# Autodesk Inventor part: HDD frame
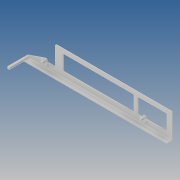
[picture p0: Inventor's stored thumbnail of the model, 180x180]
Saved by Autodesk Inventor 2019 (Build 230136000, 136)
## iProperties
Created: 2021-02
Part Number: HDD frame
Material: Všeobecné
Document SubType Name: Modeling
Designer: Martin Kočka
Density: 1 g/cm^3
Appearance: Výchozí
Author: Martin Kočka
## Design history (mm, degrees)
sketch "Náčrt1"
  geometry: L1 (-44.5, 13)-(75.5, 13); L2 (75.5, 13)-(75.5, -13); L3 (75.5, -13)-(-73.5, -13); L4 (-136.949, 0)-(119.471, 0) reference; L5 (0, -18.2)-(0, 18.2) reference; L6 (-36.5, 9)-(36.5, 9); L7 (36.5, 9)-(36.5, -7); L8 (36.5, -7)-(-36.5, -7); L9 (-36.5, -7)-(-36.5, 9); L10 (-44.5, -7)-(-44.5, 13); L11 (40.5, 9)-(70.5, 9); L12 (70.5, 9)-(70.5, -7); L13 (40.5, -7)-(40.5, 9); L14 (-100.317, -6.15)-(82.839, -6.15); L15 (-73.5, -13)-(-73.5, -11); L16 (-52.95, -6.15)-(-52.95, -7); L17 (-52.95, -7)-(-44.5, -7); L18 (45.35, -7)-(45.35, -6.15); L19 (48.65, -6.15)-(48.65, -7); L20 (-73.5, -11)-(-55.144, -4.592); L21 (45.35, -7)-(40.5, -7); L22 (70.5, -7)-(48.65, -7); C1 r 1.25 at (47, -6.15); A1 r 1.65 centre (47, -6.15) between (45.586, -7) and (45.35, -6.15); A2 r 1.65 centre (-54.6, -6.15) between (-52.95, -6.15) and (-55.144, -4.592); A3 r 1.65 centre (-54.6, -6.15) between (-52.95, -6.15) and (-55.144, -4.592); A4 r 1.65 centre (47, -6.15) between (48.65, -6.15) and (45.35, -6.15); 3 further points
  constraints: 40 end point, 8 parallel, 8 point on circle, 6 perpendicular, 5 centre point, 5 coincident, 5 point on line, 4 collinear, 4 tangent, 3 horizontal, 1 concentric, 1 vertical, 2 other
  dimensions: "d1" = 26 distance of L1.end L2.end; "d3" = 39 distance between parallel lines of L7 L2; "d4" = 6 distance between parallel lines of L3 L8; "d5" = 4 distance between parallel lines of L1 L6; "d6" = 28.5 distance from line of L2 point (47, -6.15); "d7" = 101.6 distance of point (47, -6.15) point (-54.6, -6.15); "d8" = 2.5 diameter of C1; "d10" = 6.85 distance between parallel lines of L3 L14; "d11" = 5 distance between parallel lines of L12 L2; "d12" = 4 distance between parallel lines of L7 L13; "d13" = 8 distance between parallel lines of L9 L10; "d14" = 112 distance between parallel lines of L2 L9; "d15" = 3.3 diameter of A1; "d17" = 149 distance of L2.end L3.end; "d18" = 3.3 diameter of A2; "d19" = 2 distance from line of L15.end L3
extrude "Vysunutí1" new body sketch "Náčrt1" distance "d20" = 0.9; taper "d21" = 0 deg
fillet "Zaoblení1" dims "d22" = 1
sketch "Náčrt2"
  geometry: L1 (74.5, 13)-(-43.5, 13) reference; L2 (-44.5, 12)-(-44.5, -6) reference; L3 (-45.5, -7)-(-51.954, -7) reference; L4 (-55.144, -4.592)-(-73.5, -11) reference; L5 (-73.5, -11)-(-73.5, -13) reference; L6 (-73.5, -13)-(75.5, -13) reference; L7 (75.5, -13)-(75.5, 12) reference; L8 (35.5, -7)-(-35.5, -7) reference; L9 (-36.5, -6)-(-36.5, 8) reference; L10 (-35.5, 9)-(35.5, 9) reference; L11 (36.5, 8)-(36.5, -6) reference; L12 (70.5, 8)-(70.5, -6) reference; L13 (69.5, -7)-(49.646, -7) reference; L14 (44.354, -7)-(41.5, -7) reference; L15 (40.5, -6)-(40.5, 8) reference; L16 (41.5, 9)-(69.5, 9) reference; L17 (-58.584, -5.793)-(-55.144, -4.592); L18 (-45.5, -7)-(-51.954, -7) reference; L19 (-50.691, -7)-(-51.954, -7); L20 (44.354, -7)-(41.5, -7) reference; L21 (43.091, -7)-(44.354, -7); L22 (49.646, -7)-(50.909, -7); L23 (69.5, -7)-(49.646, -7) reference; A1 r 1.65 centre (-54.6, -6.15) between (-52.953, -6.057) and (-55.144, -4.592) reference; A2 r 1.65 centre (-54.6, -6.15) between (-52.953, -6.057) and (-55.144, -4.592); A3 r 1.65 centre (47, -6.15) between (48.647, -6.057) and (45.353, -6.057) reference; A4 r 1.65 centre (47, -6.15) between (48.647, -6.057) and (45.353, -6.057); A5 r 4 centre (-54.6, -6.15) between (-58.584, -5.793) and (-50.691, -7); A6 r 4 centre (47, -6.15) between (43.091, -7) and (50.909, -7); A7 r 1 centre (74.5, 12) between (75.5, 12) and (74.5, 13) reference; A8 r 1 centre (-43.5, 12) between (-43.5, 13) and (-44.5, 12) reference; A9 r 1 centre (-45.5, -6) between (-45.5, -7) and (-44.5, -6) reference; A10 r 1 centre (-51.954, -6) between (-52.953, -6.057) and (-51.954, -7) reference; A11 r 1.65 centre (-54.6, -6.15) between (-52.953, -6.057) and (-55.144, -4.592) reference; A12 r 1 centre (-35.5, -6) between (-36.5, -6) and (-35.5, -7) reference; A13 r 1 centre (-35.5, 8) between (-35.5, 9) and (-36.5, 8) reference; A14 r 1 centre (35.5, 8) between (36.5, 8) and (35.5, 9) reference; A15 r 1 centre (35.5, -6) between (35.5, -7) and (36.5, -6) reference; A16 r 1 centre (69.5, -6) between (69.5, -7) and (70.5, -6) reference; A17 r 1 centre (49.646, -6) between (48.647, -6.057) and (49.646, -7) reference; A18 r 1.65 centre (47, -6.15) between (48.647, -6.057) and (45.353, -6.057) reference; A19 r 1 centre (44.354, -6) between (44.354, -7) and (45.353, -6.057) reference; A20 r 1 centre (41.5, -6) between (40.5, -6) and (41.5, -7) reference; A21 r 1 centre (41.5, 8) between (41.5, 9) and (40.5, 8) reference; A22 r 1 centre (69.5, 8) between (70.5, 8) and (69.5, 9) reference; A23 r 1 centre (-51.954, -6) between (-52.953, -6.057) and (-51.954, -7); A24 r 1 centre (44.354, -6) between (44.354, -7) and (45.353, -6.057) reference; A25 r 1 centre (44.354, -6) between (44.354, -7) and (45.353, -6.057); A26 r 1 centre (49.646, -6) between (48.647, -6.057) and (49.646, -7); 1 further point
  constraints: 19 point on circle, 10 end point, 7 centre point, 7 coincident, 4 point on line, 2 collinear, 2 concentric, 2 tangent
  dimensions: "d23" = 8 diameter of A5; "d24" = 8 diameter of A6
extrude "Vysunutí2" join sketch "Náčrt2" distance "d25" = 1.1; taper "d26" = 0 deg
sketch "Náčrt3"
  geometry: L1 (-55.144, -4.592)-(-58.584, -5.793) reference; L2 (-50.691, -7)-(-51.954, -7) reference; L3 (44.354, -7)-(43.091, -7) reference; L4 (50.909, -7)-(49.646, -7) reference; C1 r 1.25 at (-54.6, -6.15); C2 r 1.25 at (47, -6.15); A1 r 1 centre (-51.954, -6) between (-52.953, -6.057) and (-51.954, -7) reference; A2 r 1.65 centre (-54.6, -6.15) between (-52.953, -6.057) and (-55.144, -4.592) reference; A3 r 4 centre (-54.6, -6.15) between (-58.584, -5.793) and (-50.691, -7) reference; A4 r 4 centre (47, -6.15) between (43.091, -7) and (50.909, -7) reference; A5 r 1 centre (49.646, -6) between (48.647, -6.057) and (49.646, -7) reference; A6 r 1.65 centre (47, -6.15) between (48.647, -6.057) and (45.353, -6.057) reference; A7 r 1 centre (44.354, -6) between (44.354, -7) and (45.353, -6.057) reference; 1 further point
  constraints: 2 centre point, 2 coincident
  dimensions: "d27" = 2.5 diameter of C1; "d28" = 2.5 diameter of C2
extrude "Vysunutí3" join sketch "Náčrt3" distance "d29" = 3; taper "d30" = 0 deg
chamfer "Zkosení1" distance "d31" = 0.4; stored, may be unused: second distance "d32" = 2, angle "d33" = 45 deg
fillet "Zaoblení2" dims "d34" = 1
sketch "Náčrt5"
  geometry: L1 (0, 0.9)-(149, 0.9) reference; L2 (0, 0.9)-(2, 0.9); L3 (0, 0.9)-(0, 20.9); L4 (0, 20.9)-(2, 20.9); L5 (2, 20.9)-(2, 0.9); 2 further points
  constraints: 8 end point, 1 horizontal, 1 perpendicular, 1 point on line, 1 vertical
  dimensions: "d45" = 2 distance of L1.start L2.end; "d46" = 20 distance of L1.start L3.end
extrude "Vysunutí5" join sketch "Náčrt5" distance "d47" = 2; taper "d48" = 0 deg
fillet "Zaoblení6" dims "d51" = 1
sketch "Náčrt6"
  geometry: L1 (-59.544, -6.128)-(-73.5, -11) reference; L2 (-73.5, -11)-(-71.5, -11) reference; L3 (-71.5, -11)-(-71.5, -13) reference; L4 (-71.5, -13)-(75.5, -13) reference; L5 (75.5, -13)-(75.5, 12) reference; L6 (74.5, 13)-(-43.5, 13) reference; L7 (-44.5, 12)-(-44.5, -6) reference; L8 (-45.5, -7)-(-50.482, -7) reference; L9 (42.882, -7)-(41.5, -7) reference; L10 (40.5, -6)-(40.5, 8) reference; L11 (41.5, 9)-(69.5, 9) reference; L12 (70.5, 8)-(70.5, -6) reference; L13 (69.5, -7)-(51.118, -7) reference; L14 (35.5, -7)-(-35.5, -7) reference; L15 (-36.5, -6)-(-36.5, 8) reference; L16 (-35.5, 9)-(35.5, 9) reference; L17 (36.5, 8)-(36.5, -6) reference; L18 (-71.5, -13)-(-71.5, -11) reference; L19 (75.5, -13)-(-71.5, -13); L20 (-71.5, -13)-(-71.5, -12.5); L21 (-71.5, -12.5)-(75.5, -12.5); L22 (75.5, -12.5)-(75.5, -13); A1 r 2 centre (-57.579, -6.502) between (-59.544, -6.128) and (-59.566, -6.736) reference; A2 r 1 centre (74.5, 12) between (75.5, 12) and (74.5, 13) reference; A3 r 1 centre (-43.5, 12) between (-43.5, 13) and (-44.5, 12) reference; A4 r 1 centre (-45.5, -6) between (-45.5, -7) and (-44.5, -6) reference; A5 r 2 centre (-52.224, -7.982) between (-50.64, -9.203) and (-50.482, -7) reference; A6 r 5 centre (-54.6, -6.15) between (-59.566, -6.736) and (-50.64, -9.203) reference; A7 r 2 centre (44.624, -7.982) between (42.882, -7) and (43.04, -9.203) reference; A8 r 1 centre (41.5, -6) between (40.5, -6) and (41.5, -7) reference; A9 r 1 centre (41.5, 8) between (41.5, 9) and (40.5, 8) reference; A10 r 1 centre (69.5, 8) between (70.5, 8) and (69.5, 9) reference; A11 r 1 centre (69.5, -6) between (69.5, -7) and (70.5, -6) reference; A12 r 2 centre (49.376, -7.982) between (50.96, -9.203) and (51.118, -7) reference; A13 r 5 centre (47, -6.15) between (43.04, -9.203) and (50.96, -9.203) reference; A14 r 1 centre (-35.5, -6) between (-36.5, -6) and (-35.5, -7) reference; A15 r 1 centre (-35.5, 8) between (-35.5, 9) and (-36.5, 8) reference; A16 r 1 centre (35.5, 8) between (36.5, 8) and (35.5, 9) reference; A17 r 1 centre (35.5, -6) between (35.5, -7) and (36.5, -6) reference; 1 further point
  constraints: 8 end point, 2 parallel, 1 horizontal, 1 perpendicular, 1 point on line
  dimensions: "d52" = 0.5 distance of L19.end L20.end
extrude "Vysunutí6" join sketch "Náčrt6" distance "d53" = 5; taper "d54" = 0 deg
fillet "Zaoblení7" dims "d55" = 1
node "Těleso1"
node "Promítnutá smyčka1"
node "Promítnutá smyčka2"
node "Promítnutá smyčka3"
node "Promítnutá smyčka4"
